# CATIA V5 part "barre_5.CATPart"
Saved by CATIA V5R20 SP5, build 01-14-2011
Part number: barre_5
Bounding box of the stored display mesh (mm): x 12 to 18, y -63.814 to -37.22, z 41.132 to 73.684
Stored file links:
  M:\EU_thinkMotion\IAO_2010\iao\IAO_MMS_Groupe2\IAO_MMS_Groupe2\sdubois\sdubois\sdubois\IAO_mecanisme\barre_5.CATPart
  M:\EU_thinkMotion\IAO_2010\iao\IAO_MMS_Groupe2\IAO_MMS_Groupe2\sdubois\sdubois\sdubois\IAO_mecanisme\assembage final.CATProduct
  M:\EU_thinkMotion\IAO_2010\iao\IAO_MMS_Groupe2\IAO_MMS_Groupe2\sdubois\sdubois\sdubois\IAO_mecanisme\squelette_5.CATPart
  M:\EU_thinkMotion\IAO_2010\iao\IAO_MMS_Groupe2\IAO_MMS_Groupe2\sdubois\sdubois\sdubois\IAO_mecanisme\barre_2.CATPart
  M:\EU_thinkMotion\IAO_2010\iao\IAO_MMS_Groupe2\IAO_MMS_Groupe2\sdubois\sdubois\sdubois\IAO_mecanisme\barre_4.CATPart
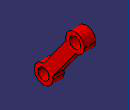
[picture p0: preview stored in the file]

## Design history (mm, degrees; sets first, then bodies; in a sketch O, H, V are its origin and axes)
External parameters (linked from other documents)
  External.largeur_barre = 6 mm
  `External.diamètre pivot en E` = 6 mm
  `External.diamètre pivot en K` = 6 mm
Set1
  Plane1: linked copy from another document
  Plane2: linked copy from another document
  Point1: linked copy from another document
  Point2: linked copy from another document
  Plane3: linked copy from another document
  Plane4: linked copy from another document
  Point3: linked copy from another document
  Point4: linked copy from another document
  DatumSurface1: linked copy from another document
  Line1: linked copy from another document
Body1 (main body)
  Sketch1 on Plane1, origin (12, 0, 0), H (0, 1, 0), V (0, 0, 1)
    line L1 (-61.2307, 47.9096) -> (-44.6361, 70.4622)
    point P1 (-61.2307, 47.9096)
    point P2 (-44.6361, 70.4622)
    line L2 (-56.398, 44.3536) -> (-39.8034, 66.9062)
    point P3 (-56.398, 44.3536)
    point P4 (-39.8034, 66.9062)
    line L3 (-44.6361, 70.4622) -> (-39.8034, 66.9062)
    point P5 (-44.6361, 70.4622)
    point P6 (-39.8034, 66.9062)
    line L4 (-61.2307, 47.9096) -> (-56.398, 44.3536)
    point P7 (-61.2307, 47.9096)
    point P8 (-56.398, 44.3536)
    reference intersected line E1 through (-51.3514, 56.2739) direction (-0.5927, -0.8055) from Plane2
    reference intersected line E2 through (-51.3514, 56.2739) direction (-0.5927, -0.8055) from Plane2
    reference projected point E3 (-61.2307, 47.9096) from Point1
    reference projected point E4 (-56.398, 44.3536) from Point2
    reference intersected line E5 through (21.0095, 22.159) direction (-0.8055, 0.5927) from Plane3
    reference intersected line E6 through (21.0095, 22.159) direction (-0.8055, 0.5927) from Plane3
    reference intersected line E7 through (0.0787, 2.7971) direction (-0.8055, 0.5927) from Plane4
    reference intersected line E8 through (0.0787, 2.7971) direction (-0.8055, 0.5927) from Plane4
    distance L1 E3 = 0
    distance E4 L2 = 0
    distance P2 E5 = 0
    distance P4 E6 = 0
    distance P3 E7 = 0
    distance P1 E8 = 0
    distance P5 P2 = 0
    distance P6 P4 = 0
    distance P1 P7 = 0
    distance P3 P8 = 0
    parallelism: L1 E1, L2 E2
  Sketch2 on Plane1, origin (12, 0, 0), H (0, 1, 0), V (0, 0, 1)
    circle A1 centre (-58.8143, 46.1316) radius 5
    point P1 (-58.8143, 46.1316)
    circle A2 centre (-42.2198, 68.6842) radius 5
    point P2 (-42.2198, 68.6842)
    reference projected point E1 (-42.2198, 68.6842) from Point3
    reference projected point E2 (-58.8143, 46.1316) from Point4
    distance E1 P2 = 0
    radius A2 = 5
    distance P1 E2 = 0
    radius A1 = 5
  Sketch3 on Plane1, origin (12, 0, 0), H (0, 1, 0), V (0, 0, 1)
    circle A1 centre (-58.8143, 46.1316) radius 3
    point P1 (-58.8143, 46.1316)
    point P2 (-42.2198, 68.6842)
    reference projected point E1 (-58.8143, 46.1316) from Point4
    reference projected point E2 (-42.2198, 68.6842) from Point3
    radius A1 = 3 {= `External.diamètre pivot en E` /2}
    distance P1 E1 = 0
    distance P2 E2 = 0
  Pad1: profile Sketch1, direction (1, 0, 0), length 6 {= 3*External.largeur_barre -12mm}, opposite side length 0 {= 12mm-2*External.largeur_barre}
  Pad2: profile Sketch2, direction (1, 0, 0), length 6 {= 3*External.largeur_barre -12mm}, opposite side length 0 {= 12mm-2*External.largeur_barre}
  Pocket1: profile Sketch3, direction (1, 0, 0), length 6 {= 3*External.largeur_barre -12mm}, opposite side length 0 {= 12mm-2*External.largeur_barre}
  Sketch4 on face of Pad2, origin (18, 0, 0), H (0, 1, 0), V (0, 0, 1)
    circle A1 centre (-42.2198, 68.6842) radius 3
    point P1 (-42.2198, 68.6842)
    reference projected point E1 (-42.2198, 68.6842) from Line1
    distance P1 E1 = 0
    radius A1 = 3 {= `External.diamètre pivot en K` /2}
  Pocket2: profile Sketch4, direction (-1, 0, 0), length 6 {= External.largeur_barre}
